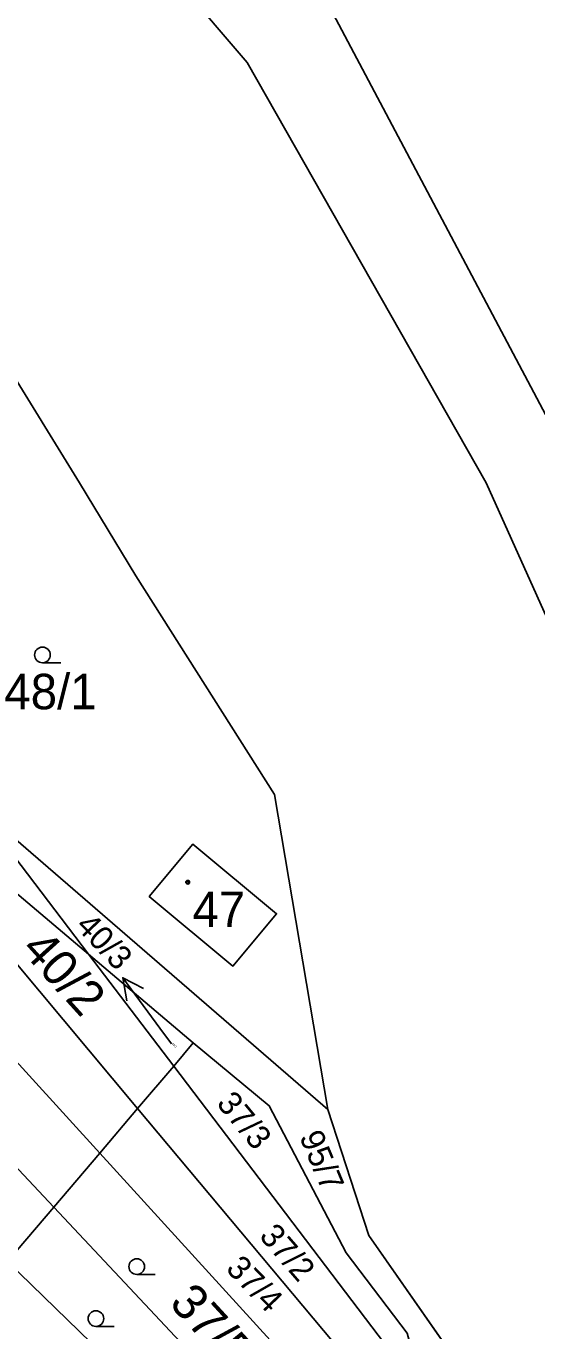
# Model space of a CAD drawing. Extents: x -598233 to -596890, y -1157848 to -1156431.
# Drawn here: x -597327.1 to -597302.6, y -1157018.9 to -1156956.3 of the extents above; entities that cross this region are included whole.
import ezdxf

# ---------------------------------------------------------------- set-up
doc = ezdxf.new("R2010")
doc.units = 0
for name, color, linetype in [('Level 1', 7, 'Continuous'), ('Level 4', 7, 'Continuous'), ('Level 5', 7, 'Continuous'), ('Level 57', 7, 'Continuous'), ('Level 60', 7, 'Continuous'), ('Vrstva 54', 7, 'Continuous'), ('Vrstva 60', 7, 'Continuous')]:
    doc.layers.add(name, color=color, linetype=linetype)

msp = doc.modelspace()

# ---------------------------------------------------------------- linework, layer by layer
at = {"layer": 'Level 1'}
for points in [[(-597352.98, -1156781.78), (-597351.14, -1156788.98), (-597350.85, -1156790.02), (-597349.99, -1156803.32), (-597352.22, -1156815.94), (-597355.53, -1156830.13), (-597359.3, -1156851.45), (-597357.41, -1156870.91), (-597352.65, -1156887.77), (-597341.75, -1156910.83), (-597324.77, -1156940.32), (-597312.64, -1156955.18), (-597301.74, -1156975.75), (-597294.59, -1156991.63), (-597282.12, -1157016.64), (-597260.07, -1157046.49), (-597257.21, -1157055.98), (-597259.55, -1157090.81), (-597266.67, -1157100.7), (-597269.15, -1157107.01)], [(-597356.25, -1156785.65), (-597354.86, -1156802.73), (-597357.2, -1156818.06), (-597359.11, -1156829.7), (-597363.07, -1156850.99), (-597362.74, -1156869.36), (-597357.1, -1156890.05), (-597346.03, -1156913.02), (-597329.57, -1156942.78), (-597316.48, -1156958.06), (-597305.02, -1156978.21), (-597297.88, -1156994.09), (-597286.04, -1157019.58), (-597274.21, -1157034.49)], [(-597315.54, -1157068.55), (-597316.36, -1157049.69), (-597316.57, -1157044.86), (-597315.03, -1157042.41), (-597313.54, -1157040.04), (-597313.01, -1157039.2), (-597311.84, -1157037.35), (-597310.56, -1157035.31), (-597309.44, -1157033.52), (-597308.22, -1157031.59), (-597306.57, -1157028.96), (-597305.61, -1157027.44), (-597304.81, -1157026.14), (-597303.64, -1157024.31), (-597310.64, -1157014.28), (-597312.61, -1157008.25), (-597315.16, -1156993.14), (-597321.82, -1156982.66), (-597324.52, -1156978.21), (-597328.01, -1156972.52), (-597345.28, -1156956.63), (-597347.92, -1156950.58)], [(-597312.61, -1157008.25), (-597315.16, -1156993.14), (-597321.82, -1156982.66), (-597324.52, -1156978.21), (-597328.01, -1156972.52)], [(-597324.09, -1157000.8), (-597334.28, -1156992.19)], [(-597334.71, -1156992.68), (-597321.73, -1157008.19)], [(-597329.6, -1156993.56), (-597312.61, -1157008.25)], [(-597329.6, -1156993.56), (-597324.09, -1157000.8)], [(-597337.1, -1156995.44), (-597323.54, -1157010.33)], [(-597319.08, -1156995.52), (-597321.17, -1156998.03), (-597317.16, -1157001.37), (-597315.07, -1156998.86), (-597319.08, -1156995.52)], [(-597339.53, -1156998.24), (-597325.74, -1157012.93)], [(-597319.06, -1157005.05), (-597324.09, -1157000.8)], [(-597324.09, -1157000.8), (-597320, -1157006.16)], [(-597319.06, -1157005.05), (-597320, -1157006.16)], [(-597319.06, -1157005.05), (-597315.42, -1157008.06), (-597311.74, -1157015.11), (-597308.81, -1157018.97), (-597307.97, -1157021.99)], [(-597320, -1157006.16), (-597321.73, -1157008.19)], [(-597320, -1157006.16), (-597307.97, -1157021.99)], [(-597321.73, -1157008.19), (-597323.54, -1157010.33)], [(-597306.87, -1157025.93), (-597321.73, -1157008.19)], [(-597304.81, -1157026.14), (-597303.64, -1157024.31), (-597310.64, -1157014.28), (-597312.61, -1157008.25)], [(-597323.54, -1157010.33), (-597325.74, -1157012.93)], [(-597323.54, -1157010.33), (-597307.86, -1157027.54)], [(-597325.74, -1157012.93), (-597327.96, -1157015.53)], [(-597325.74, -1157012.93), (-597309.51, -1157030.22)], [(-597327.96, -1157015.53), (-597310.75, -1157032.25)]]:
    msp.add_lwpolyline(points, dxfattribs=at)
at = {"layer": 'Level 5'}
for p, q in [((-597326.29, -1156986.83), (-597325.415, -1156986.83)), ((-597321.77, -1157016.15), (-597320.895, -1157016.15)), ((-597323.73, -1157018.64), (-597322.855, -1157018.64))]:
    msp.add_line(p, q, dxfattribs=at)
for centre, radius in [((-597326.29, -1156986.455), 0.375), ((-597319.33, -1156997.35), 0.09), ((-597319.33, -1156997.35), 0.0521), ((-597321.77, -1157015.775), 0.375), ((-597323.73, -1157018.265), 0.375)]:
    msp.add_circle(centre, radius, dxfattribs=at)
at = {"layer": 'Level 57'}
for p, q in [((-597320.658, -1157004.344), (-597322.44, -1157001.93)), ((-597320.1, -1157005.1), (-597320.658, -1157004.344))]:
    msp.add_line(p, q, dxfattribs=at)
msp.add_lwpolyline([(-597322.248, -1157003.032), (-597322.44, -1157001.93), (-597321.444, -1157002.438)], dxfattribs=at)
at = {"layer": 'Level 60'}
for points in [[(-597352.65, -1156887.77), (-597341.75, -1156910.83), (-597324.77, -1156940.32), (-597312.64, -1156955.18), (-597301.74, -1156975.75), (-597294.59, -1156991.63), (-597282.12, -1157016.64), (-597260.07, -1157046.49), (-597257.21, -1157055.98), (-597259.55, -1157090.81), (-597266.67, -1157100.7), (-597269.15, -1157107.01), (-597274.89, -1157120.22), (-597305.88, -1157145.91)], [(-597335.53, -1157161.51), (-597307.94, -1157142.59), (-597277.61, -1157115.85), (-597273.93, -1157106.57), (-597266.72, -1157090.16), (-597261.79, -1157055.57), (-597265.05, -1157046.04), (-597272.14, -1157037.1), (-597274.21, -1157034.49), (-597286.04, -1157019.58), (-597297.88, -1156994.09), (-597305.02, -1156978.21), (-597316.48, -1156958.06), (-597329.57, -1156942.78), (-597346.03, -1156913.02), (-597357.1, -1156890.05)], [(-597357.1, -1156890.05), (-597346.03, -1156913.02), (-597329.57, -1156942.78), (-597316.48, -1156958.06), (-597305.02, -1156978.21), (-597297.88, -1156994.09), (-597286.04, -1157019.58), (-597274.21, -1157034.49), (-597275.62, -1157045), (-597275.45, -1157056.28)], [(-597315.54, -1157068.55), (-597316.36, -1157049.69), (-597316.57, -1157044.86), (-597315.03, -1157042.41), (-597313.54, -1157040.04), (-597313.01, -1157039.2), (-597311.84, -1157037.35), (-597310.56, -1157035.31), (-597309.44, -1157033.52), (-597308.22, -1157031.59), (-597306.57, -1157028.96), (-597305.61, -1157027.44), (-597304.81, -1157026.14), (-597303.64, -1157024.31), (-597310.64, -1157014.28), (-597312.61, -1157008.25), (-597315.16, -1156993.14), (-597321.82, -1156982.66), (-597324.52, -1156978.21), (-597328.01, -1156972.52), (-597345.28, -1156956.63), (-597347.92, -1156950.58)]]:
    msp.add_lwpolyline(points, dxfattribs=at)
for points in [[(-597312.61, -1157008.25), (-597329.6, -1156993.56), (-597331.38, -1156991.22), (-597337.44, -1156983), (-597328.01, -1156972.52), (-597324.52, -1156978.21), (-597321.82, -1156982.66), (-597315.16, -1156993.14)], [(-597339.35, -1156985.13), (-597329.6, -1156993.56), (-597324.09, -1157000.8), (-597334.28, -1156992.19), (-597337.2, -1156989.71), (-597339.13, -1156987.4), (-597345.53, -1156980.07), (-597345.89, -1156979.53)], [(-597320, -1157006.16), (-597321.73, -1157008.19), (-597334.71, -1156992.68), (-597334.28, -1156992.19), (-597324.09, -1157000.8)], [(-597334.71, -1156992.68), (-597321.73, -1157008.19), (-597323.54, -1157010.33), (-597337.1, -1156995.44)], [(-597315.42, -1157008.06), (-597319.06, -1157005.05), (-597324.09, -1157000.8), (-597329.6, -1156993.56), (-597312.61, -1157008.25), (-597310.64, -1157014.28), (-597303.64, -1157024.31), (-597304.81, -1157026.14), (-597307.97, -1157021.99), (-597308.81, -1157018.97), (-597311.74, -1157015.11)], [(-597337.1, -1156995.44), (-597323.54, -1157010.33), (-597325.74, -1157012.93), (-597339.53, -1156998.24)], [(-597321.17, -1156998.03), (-597319.08, -1156995.52), (-597315.07, -1156998.86), (-597317.16, -1157001.37)], [(-597319.08, -1156995.52), (-597321.17, -1156998.03), (-597317.16, -1157001.37), (-597315.07, -1156998.86)], [(-597327.96, -1157015.53), (-597342.37, -1157001.53), (-597339.53, -1156998.24), (-597325.74, -1157012.93)], [(-597319.06, -1157005.05), (-597320, -1157006.16), (-597324.09, -1157000.8)], [(-597319.06, -1157005.05), (-597315.42, -1157008.06), (-597311.74, -1157015.11), (-597308.81, -1157018.97), (-597307.97, -1157021.99), (-597320, -1157006.16)], [(-597306.87, -1157025.93), (-597321.73, -1157008.19), (-597320, -1157006.16), (-597307.97, -1157021.99)], [(-597321.73, -1157008.19), (-597306.87, -1157025.93), (-597307.86, -1157027.54), (-597323.54, -1157010.33)], [(-597323.54, -1157010.33), (-597307.86, -1157027.54), (-597309.51, -1157030.22), (-597325.74, -1157012.93)], [(-597310.75, -1157032.25), (-597327.96, -1157015.53), (-597325.74, -1157012.93), (-597309.51, -1157030.22)], [(-597329.94, -1157017.87), (-597327.96, -1157015.53), (-597310.75, -1157032.25), (-597311.89, -1157034.11), (-597313.29, -1157032.85), (-597312.81, -1157032.3), (-597317.85, -1157027.96), (-597318.23, -1157028.41)]]:
    msp.add_lwpolyline(points, close=True, dxfattribs=at)
at = {"layer": 'Vrstva 54'}
for p, q in [((-597328.01, -1156972.52), (-597324.52, -1156978.21)), ((-597324.52, -1156978.21), (-597321.82, -1156982.66)), ((-597321.82, -1156982.66), (-597315.16, -1156993.14)), ((-597315.16, -1156993.14), (-597312.61, -1157008.25)), ((-597312.61, -1157008.25), (-597310.64, -1157014.28)), ((-597310.64, -1157014.28), (-597303.64, -1157024.31))]:
    msp.add_line(p, q, dxfattribs=at)
at = {"layer": 'Vrstva 60'}
for points in [[(-597352.65, -1156887.77), (-597341.75, -1156910.83), (-597324.77, -1156940.32), (-597312.64, -1156955.18), (-597301.74, -1156975.75), (-597294.59, -1156991.63), (-597282.12, -1157016.64), (-597260.07, -1157046.49), (-597257.21, -1157055.98), (-597259.55, -1157090.81), (-597266.67, -1157100.7), (-597269.15, -1157107.01), (-597273.23, -1157122.89), (-597280.79, -1157141.61), (-597300.02, -1157155.33)], [(-597347.92, -1156950.58), (-597345.28, -1156956.63), (-597328.01, -1156972.52), (-597324.52, -1156978.21), (-597321.82, -1156982.66), (-597315.16, -1156993.14), (-597312.61, -1157008.25), (-597310.64, -1157014.28), (-597303.64, -1157024.31), (-597304.81, -1157026.14), (-597305.61, -1157027.44), (-597306.57, -1157028.96), (-597308.22, -1157031.59), (-597309.44, -1157033.52), (-597310.56, -1157035.31), (-597311.84, -1157037.35), (-597313.01, -1157039.2), (-597313.54, -1157040.04), (-597315.03, -1157042.41), (-597316.57, -1157044.86), (-597315.54, -1157068.55)], [(-597315.54, -1157068.55), (-597316.57, -1157044.86), (-597315.03, -1157042.41), (-597313.54, -1157040.04), (-597313.01, -1157039.2), (-597311.84, -1157037.35), (-597310.56, -1157035.31), (-597309.44, -1157033.52), (-597308.22, -1157031.59), (-597306.57, -1157028.96), (-597305.61, -1157027.44), (-597304.81, -1157026.14), (-597303.64, -1157024.31), (-597310.64, -1157014.28), (-597312.61, -1157008.25), (-597315.16, -1156993.14), (-597321.82, -1156982.66), (-597324.52, -1156978.21), (-597328.01, -1156972.52), (-597345.28, -1156956.63), (-597347.92, -1156950.58)]]:
    msp.add_lwpolyline(points, dxfattribs=at)

# ---------------------------------------------------------------- texts
at = {"layer": 'Level 4'}
for s, p in [('48/1', (-597328.12, -1156989.06)), ('47', (-597319.101, -1156999.5))]:
    msp.add_text(s, height=1.7, dxfattribs=at).set_placement(p)
for s, height, rotation, p in [('40/2', 1.7, 312.16473, (-597327.37, -1157000.61)), ('40/3', 0.1, 313.40097, (-597320.1, -1157005.1)), ('37/3', 1.14, 309.5226, (-597317.99, -1157007.97)), ('95/7', 1.14, 292.77054, (-597313.99, -1157009.54)), ('37/2', 1.14, 310.89906, (-597315.943, -1157014.336)), ('37/4', 1.14, 313.90992, (-597317.548, -1157015.917)), ('37/5', 1.7, 312.5673, (-597320.264, -1157017.566))]:
    msp.add_text(s, height=height, rotation=rotation, dxfattribs=at).set_placement(p)
at = {"layer": 'Level 57'}
msp.add_text('40/3', height=1.14, rotation=313.40097, dxfattribs=at).set_placement((-597324.75, -1156999.487))

doc.saveas('drawing.dxf')
